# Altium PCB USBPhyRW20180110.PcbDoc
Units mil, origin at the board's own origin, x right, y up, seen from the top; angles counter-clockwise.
Board outline 2170 x 955 mil, 2 copper layers (Top Layer, Bottom Layer); 40 components, 26 nets, 144 pads, 49 vias.
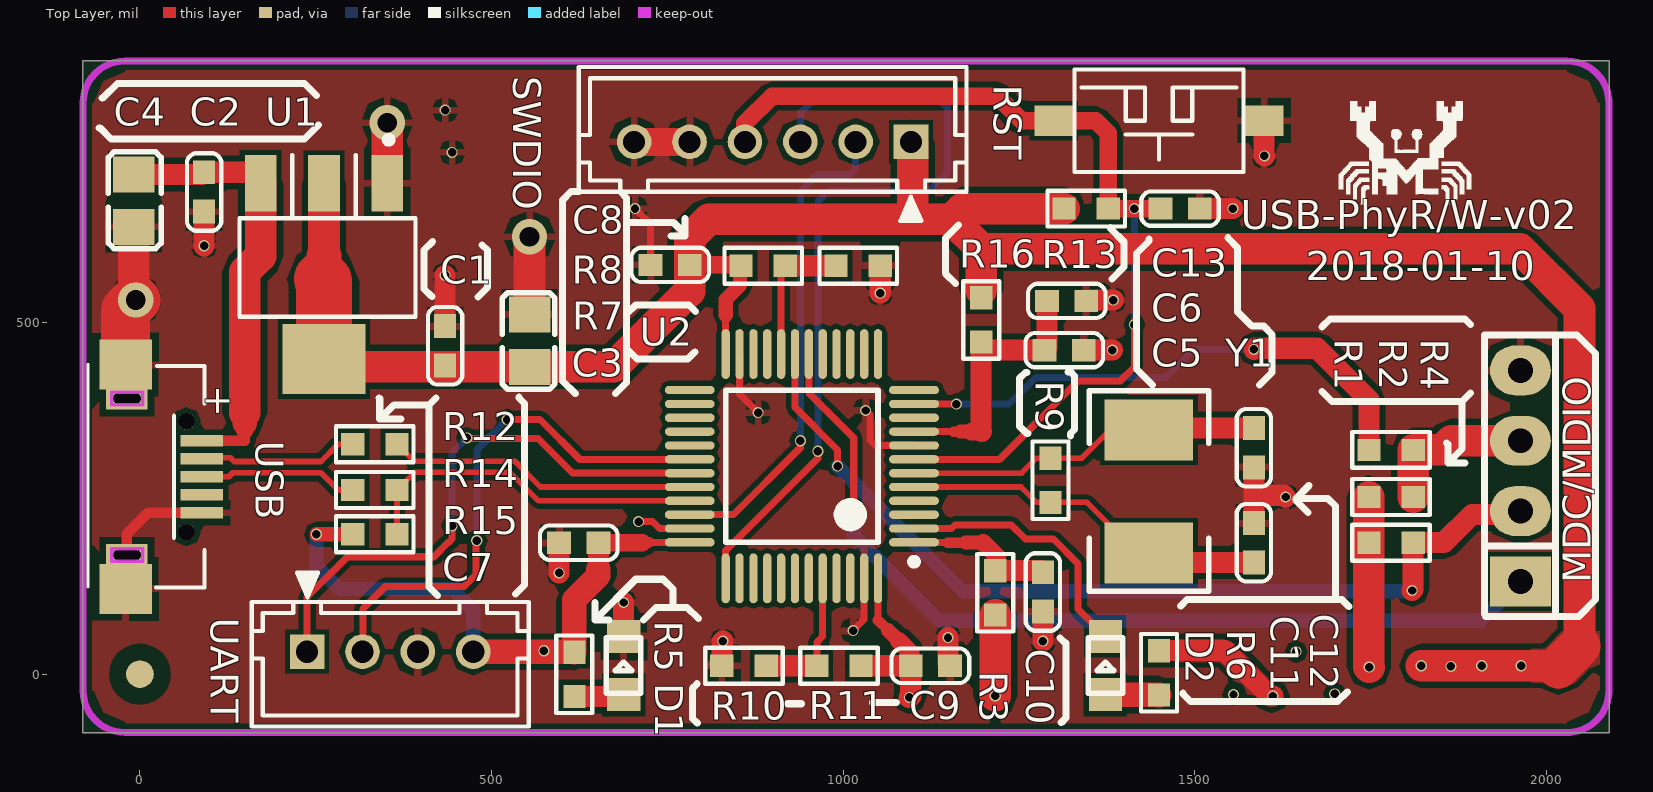
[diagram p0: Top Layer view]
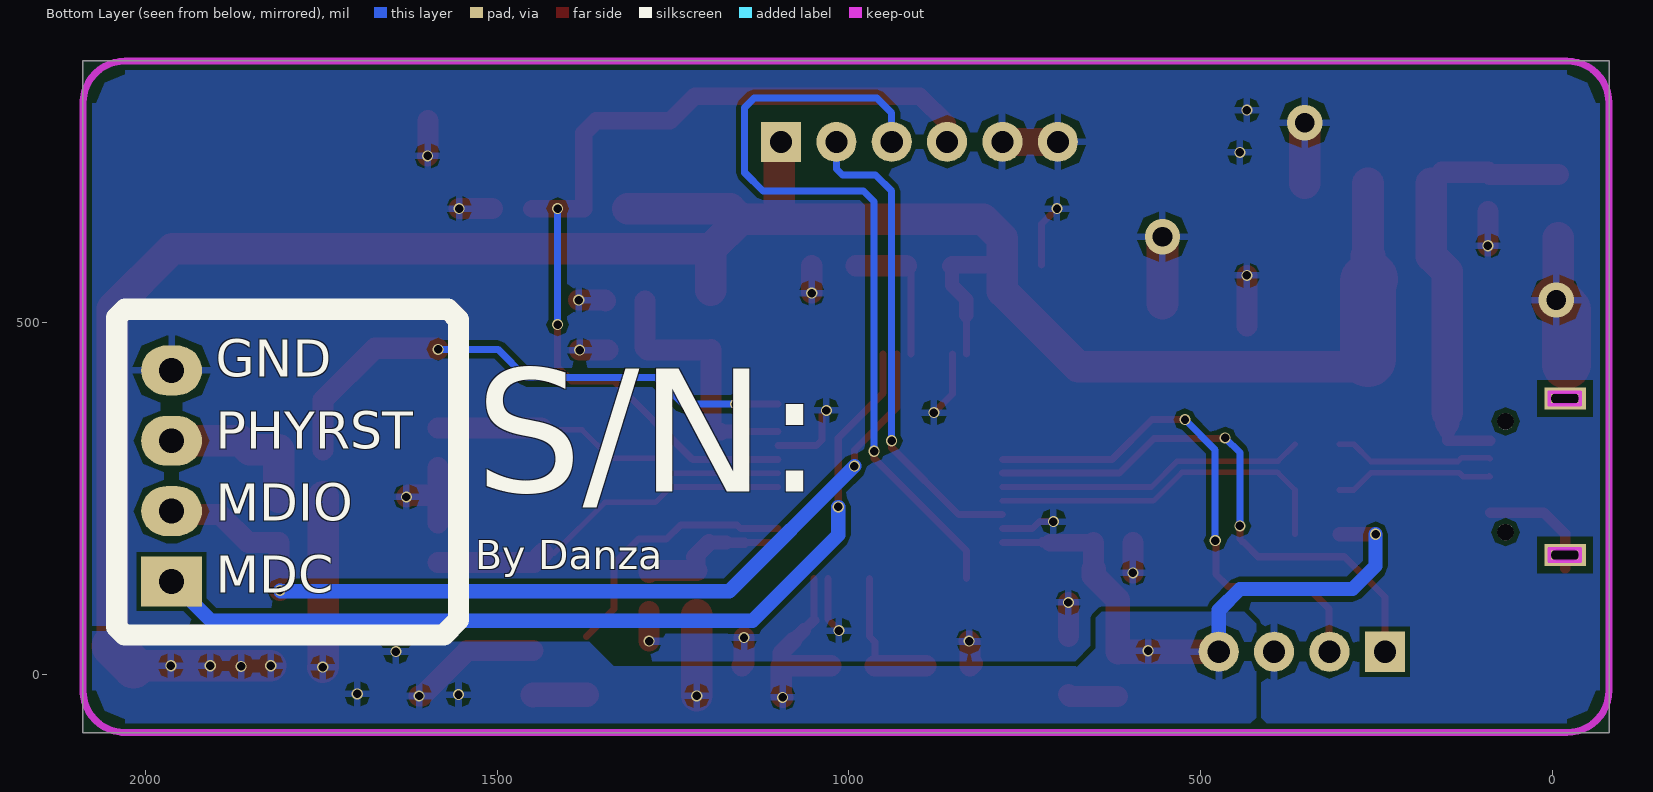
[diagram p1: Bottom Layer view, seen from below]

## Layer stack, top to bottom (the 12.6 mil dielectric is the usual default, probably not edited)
Top Solder: solder mask 0.4, Solder Resist, Dk 3.5
Top Layer: signal copper 1.4
Dielectric 1: dielectric 12.6, FR-4, Dk 4.8
Bottom Layer: signal copper 1.4
Bottom Solder: solder mask 0.4, Solder Resist, Dk 3.5

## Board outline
754,872 2089,872 2089,-63 2089,-73 2089,-83 -81,-83 -81,862 -81,872

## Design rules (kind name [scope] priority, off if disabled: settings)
Clearance [All] p1: gap=7
ComponentClearance [All] p1: gap=3 collisioncheckmode=3 verticalgap=7 showdistances=FALSE
DiffPairsRouting [All] p1: maxlimit=8 minlimit=8 mostfreqgap=8 toplayer_minwidth=8 toplayer_maxwidth=30 toplayer_prefwidth=15 bottomlayer_minwidth=8 bottomlayer_maxwidth=30 bottomlayer_prefwidth=15 maxuncoupledlength=500
PolygonConnect [All] p1: connectstyle=Relief reliefconductorwidth=10 reliefentries=4 polygonreliefangle="90 Angle" airgapwidth=10
RoutingVias [All] p1: holewidth=28 width=50 viastyle="Through Hole" minholewidth=10 minwidth=10 maxholewidth=100 maxwidth=100
SilkToSilkClearance [All] p1 off: silktosilkclearance=10
SolderMaskExpansion [All] p1: expansion=4
Width [All] p1: maxlimit=100 minlimit=8 preferedwidth=10 minimp=50.000000 maximp=50.000000 favimp=50.000000
27 further rules are at their usual default settings.

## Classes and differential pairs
component class CoreBoard: C1 C2 C3 C4 C5 C6 C7 C8 C9 C10 C11 C12 C13 D1 D2 MDC/MDIO/RST#/GND R1 R2 R3 R4 R5 R6 R7 R9 R10 R12 R13 R14 r16 RST SWDIO U1 UART USB Y1
differential pair CLK8M: +OSC_OUT -OSC_IN
differential pair USB_2: +DM_PA11 -DP_PA12
differential pair USB_1: +NetR12_2 -NetR14_2

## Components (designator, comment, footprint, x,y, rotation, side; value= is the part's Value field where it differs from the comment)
C1 "0.1uf" C0603 434,467 r90 top
C2 "0.1uf" C0603 91.24,685.74 r270 top
C3 "10uf" CAP-0805 554,437 r90 top
C4 "10uf" CAP-0805 -8.76,710.74 r270 top
C5 "1uf" C0603 1314.2,460.74 r0 top
C6 "0.1uf" C0603 1317.74,530.74 r0 top
C7 "0.1uf" C0603 624,187 r180 top
C8 "0.1uf" C0603 754,582 r180 top
C9 "0.1uf" C0603 1124,12 r0 top
C10 "0.1uf" C0603 1284,117 r270 top
C11 "20pF" C0603 1584,187 r90 top
C12 "20pF" C0603 1584,322 r90 top
C13 "0.1uf" C0603 1479,662 r180 top
D1 "LED-GREEN" LED-0805 687.74,9.76 r270 top
D2 "LED-GREEN" LED-0805 1372.74,9.76 r270 top
MDC/MDIO "CN_UART" SIP4P-2.54mm 1963,132 r0 top (schematic designator CN3)
R1 "1.5K/NC" R0603 1779,187 r180 top
R2 "50k/NC" R0603 1779,252 r0 top
R3 "0R/NC" R0603 1216.24,115.74 r270 top
R4 "0R" R0603 1779,319 r0 top
R5 "1K" R0603 617.74,-0.24 r270 top
R6 "1K" R0603 1449,2 r270 top
R7 "10K" R0603 1021.24,580.82 r180 top
R8 "10K/NC" R0603 886.24,580.82 r180 top
R9 "1M" R0603 1294.75,275.74 r270 top
R10 "10K" R0603 859,12 r0 top
R11 "10K/NC" R0603 994,12 r0 top
R12 "20R" R0603 334,327 r180 top
R13 "10K" R0603 1345.5,662 r180 top
R14 "20R" R0603 334,262 r180 top
R15 "4K7" R0603 334,199 r0 top
R16 "0R" R0603 1196.24,503.74 r270 top (schematic designator L1)
RST "KEYPAD/NC" SWITCH_T06B 1449,787 r180 top (schematic designator SW1)
SWDIO "DNP/NC" CON_SIP6BOX_2MM 1096.48,758.97 r180 top (schematic designator SWD)
U1 "LM1117-3.3V" SOT-223 269,577 r180 top
U2 "STM32F101C8T6" LQFP48_N 941.24,295.74 r180 top
UART "CN_UART/NC" CON_SIP4BOX_2MM 237.78,30.03 r0 top (schematic designator CN1)
USB "MICROUSB" MICRO-USB 1.24,280.74 r270 top
Y1 "8M" 5032-2P 1434.75,260.74 r270 top
? "Comment" MARK 0,0 r270 top

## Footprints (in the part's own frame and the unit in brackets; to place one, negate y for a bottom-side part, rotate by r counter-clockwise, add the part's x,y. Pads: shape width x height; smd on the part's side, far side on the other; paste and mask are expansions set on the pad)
5032-2P [mm]
  rect 2.2x3.2 smd: 1(-2.2,0) 2(2.25,0)
  silkscreen extent -3.62,-2.16 3.62,2.16
C0603 [mm]
  rect 0.86x0.8 smd: 1(-0.71,0) 2(0.71,0)
  silkscreen extent -1.4,-0.62 1.4,0.62
CAP-0805 [mm]
  rect 1.3x1.5 smd: 1(0,0) 2(1.9,0)
  silkscreen extent -0.82,-0.91 2.68,0.99
CON_SIP4BOX_2MM [mm]
  rect 1.25x1.25 / inner rect 1.25x1.25 / far side rect 1.45x1.45 hole 0.8: 1(0,0.05)
  round 1.25 / inner round 1.25 / far side round 1.45 hole 0.8: 2(2,0.05) 3(4,0.05) 4(6,0.05)
  silkscreen extent -2,-2.65 8,2.91
CON_SIP6BOX_2MM [mm]
  rect 1.25x1.25 / inner rect 1.25x1.25 / far side rect 1.45x1.45 hole 0.8: 1(0,0.05)
  round 1.25 / inner round 1.25 / far side round 1.45 hole 0.8: 2(2,0.05) 3(4,0.05) 4(6,0.05) 5(8,0.05) 6(10,0.05)
  silkscreen extent -2,-2.65 12,2.91
LED-0805 [mm]
  rect 1.2x1.2 smd: 1(-1.116,0.003) 2(0.984,0.003)
  silkscreen extent -1.07,-0.62 0.93,0.63
LQFP48_N [mm]
  oval 1.8x0.3 smd: 1(-4.05,2.75) 2(-4.05,2.25) 3(-4.05,1.75) 4(-4.05,1.25) 5(-4.05,0.75) 6(-4.05,0.25) 7(-4.05,-0.25) 8(-4.05,-0.75) 9(-4.05,-1.25) 10(-4.05,-1.75) 11(-4.05,-2.25) 12(-4.05,-2.75) 25(4.05,-2.75) 26(4.05,-2.25) 27(4.05,-1.75) 28(4.05,-1.25) 29(4.05,-0.75) 30(4.05,-0.25) 31(4.05,0.25) 32(4.05,0.75) 33(4.05,1.25) 34(4.05,1.75) 35(4.05,2.25) 36(4.05,2.75)
  oval 0.3x1.8 smd: 13(-2.75,-4.05) 14(-2.25,-4.05) 15(-1.75,-4.05) 16(-1.25,-4.05) 17(-0.75,-4.05) 18(-0.25,-4.05) 19(0.25,-4.05) 20(0.75,-4.05) 21(1.25,-4.05) 22(1.75,-4.05) 23(2.25,-4.05) 24(2.75,-4.05) 37(2.75,4.05) 38(2.25,4.05) 39(1.75,4.05) 40(1.25,4.05) 41(0.75,4.05) 42(0.25,4.05) 43(-0.25,4.05) 44(-0.75,4.05) 45(-1.25,4.05) 46(-1.75,4.05) 47(-2.25,4.05) 48(-2.75,4.05)
  silkscreen extent -4.18,-2.75 2.75,3.57
MARK [mm]
  round 1 smd paste-1.016 mask+0.5: ""(0,0)
  Top Layer pour cut-out: -1.109,0 -1.072,-0.287 -0.961,-0.555 -0.785,-0.785 -0.555,-0.961 -0.287,-1.072 0,-1.109 0,-1.109 0.287,-1.072 0.555,-0.961 0.785,-0.785 0.961,-0.555 1.072,-0.287 1.109,0 1.109,0 1.072,0.287 0.961,0.555 0.785,0.785 0.555,0.961 0.287,1.072 0,1.109 0,1.109 -0.287,1.072 -0.555,0.961 -0.785,0.785 -0.961,0.555 -1.072,0.287 -1.109,0
MICRO-USB [mm]
  rect 0.4x1.55 smd: 1(-1.3,2.2) 2(-0.65,2.2) 3(0,2.2) 4(0.65,2.2) 5(1.3,2.2)
  rect 1.8x1.9 smd: 6(-4.05,-0.55) 6(4.05,-0.55)
  rect 0.8x1.5 hole 0.4 slot 1 at 90 deg: 6(-2.825,-0.5) 6(2.825,-0.5)
  round 0.6 hole 0.6 unplated: ""(-2,1.65) ""(2,1.65)
  Keep-Out Layer lines w0.127: 3.054,-1.043 3.054,0.075 2.596,0.075 2.596,-1.043 3.054,-1.043 ; -2.596,-1.043 -2.596,0.075 -3.054,0.075 -3.054,-1.043 -2.596,-1.043
  silkscreen extent -4.06,-1.91 4,2.3
R0603 [mm]
  rect 0.84x0.8 smd: 1(-0.8,0) 2(0.8,0)
  silkscreen extent -1.4,-0.65 1.4,0.65
SIP4P-2.54mm [mm]
  rect 2.2x1.8 hole 0.9: 1(0,0)
  oval 2.2x1.8 hole 0.9: 2(0,2.54) 3(0,5.08) 4(0,7.62)
  silkscreen extent -1.29,-1.27 1.27,8.9
SOT-223 [mil]
  rect 45x80 smd: 1(-82.76,-121.26) 2(7.24,-121.26) 3(97.24,-121.26)
  rect 118x100 smd: 4(7.24,128.74)
  silkscreen extent -123,-188 127,69
SWITCH_T06B [mm]
  rect 1.4x1.1 smd: 1(-3.8,0) 2(3.8,0)
  silkscreen extent -3.05,-1.85 3.05,1.85

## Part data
C1 C2 C5 C6 C7 C8 C9 C10 C13: library part CAP_1, "Capacitor"
C3 C4: library part CAPACITOR, "Capacitor"
C11 C12: library part CAP, "Capacitor"
D1 D2: library part LED
MDC/MDIO UART: library part CON4
R1 R2 R3 R4 R5 R6 R7 R8 R9 R10 R11 R12 R13 R14: library part RES1
R16: library part INDUCTOR1
RST: library part PUSHBUTTON_TSKB-2L_0
SWDIO: library part CON6
U1: library part LM1117
U2: "STM32 ARM-based 32-bit MCU with 64 Kbytes Flash, 48-pin LQFP, Industrial Temperature"
Y1: library part CRYSTAL, "Crystal"

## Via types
v1: diameter 15.75, hole 12, Top Layer to Bottom Layer, 46 vias
v2: diameter 50, hole 28, Top Layer to Bottom Layer, 3 vias

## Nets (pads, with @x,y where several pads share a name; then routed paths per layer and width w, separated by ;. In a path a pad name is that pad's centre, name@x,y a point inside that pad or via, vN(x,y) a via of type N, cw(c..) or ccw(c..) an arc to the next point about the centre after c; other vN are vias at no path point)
BOOT0: R10.2 R11.1 U2.44 | length 199.7
  Top Layer w10: R11.1 962.5,45.5 970.77,53.77 U2.44
  Top Layer w30: R10.2 R11.1
BOOT1: R7.2 R8.1 U2.20 | length 200.1
  Top Layer w10: U2.20 911.72,574.8 R8.1
  Top Layer w30: R8.1 R7.2
DM_PA11: R12.1 U2.32 | length 441.5
  Top Layer w8: R12.1 389.5,303 533,303 569.79,266.21 U2.32
DP_PA12: R14.1 R15.2 U2.33 | length 506.4
  Top Layer w8: R15.2 R14.1 390.5,287 526.37,287 566.84,246.53 U2.33
GND: C1.2 C2.2 C3.2 C4.2 C5.2 C6.2 C7.2 C8.2 C9.2 C10.2 C11.2 C12.1 C13.1 D1.1 MDC/MDIO.4 R7.1 R10.1 RST.1 SWDIO.5 SWDIO.6 U1.1 U2.8 U2.23 U2.35 U2.47 UART.3 USB.5 USB.6 | length 1742.8
  Top Layer w10: v1(704,662) 726.05,639.95 C8.2 ; v1(709,217) 729,217 738.84,207.16 U2.35 ; U2.23 852.66,398.34 v1(879,372) ; v1(1014,62) 1029.83,77.83 U2.47 ; v1(1032,375) 1038,369 1038,333 1045.73,325.27 U2.8
  Top Layer w15: USB.6@-18.44,150.52 -18.44,169.52 -18.44,199.56 11.56,229.56 USB.5
  Top Layer w30: v1(91.24,609.24) C2.2 ; C1.2 v1(434,567) ; v1(596.05,144.05) C7.2 ; D1.1 v1(687.86,102) ; R10.1@824,15.5 R10.1 827.5,45.5 v1(829,47) ; v1(1052.74,542) R7.1 ; v1(1149,52) 1149,14.95 C9.2 ; v1(1284,47) C10.2 ; C5.2 v1(1382.74,460.74) ; C6.2 1346.95,532 v1(1384,532) ; C13.1 v1(1554,662) ; C11.2 1584,254.5 ; C12.1 1584,254.5 ; RST.1 1598.61,737.39 v1(1599,737) ; v1(1629,252) 1626.5,254.5 1584,254.5
  Top Layer w40: SWDIO.6 SWDIO.5
  Top Layer w45: C4.2@-8.76,620.74 -8.76,534.76 v2(-6,532) ; U1.1 v2(351.76,784.24) ; C3.2@554,527 v2(554,622)
  Top Layer w70: USB.6@-20.41,440.19 -20.41,517.59 v2(-6,532)
  other v1: 444,742 434,802
NetD1_2: D1.2 R5.2 | length 71.3
  Top Layer w30: R5.2 685.1,-31.74 D1.2
NetD2_2: D2.2 R6.2 | length 76.4
  Top Layer w35: D2.2 1448.49,-28.98 R6.2
NetQ1_1: 
NetR12_2: R12.2 USB.2 | length 227.8
  Top Layer w8: USB.2 89.53,308 128.5,308 134,302.5 257.47,302.5 281.97,327 R12.2
NetR14_2: R14.2 USB.3 | length 229
  Top Layer w8: USB.3@89.12,282 USB.3 126.24,280.74 132,286.5 257.47,286.5 281.97,262 R14.2
NRST: C13.2 R13.1 RST.2 SWDIO.4 U2.7 | length 1359.8
  Top Layer w10: U2.7 1222.58,305.58 1334,417 1394,417 1414,437 v1(1414,497) v1@1414,502
  Top Layer w25: SWDIO.4 860.26,783.26 899,822 1219,822 1254,787 RST.2 1359,787 1376.99,769.01 R13.1 v1(1414.02,662) C13.2
  Bottom Layer w10: v1(1414,497) v1(1414.02,662)
OSC_IN: C11.1 R9.2 U2.5 Y1.2 | length 527.7
  Top Layer w8: U2.5 1253.03,266.21 1275,244.24 R9.2 1346.76,244.24 1418.84,172.16 Y1.2
  Top Layer w30: Y1.2 1447.86,159.05 C11.1
OSC_OUT: C12.2 R9.1 U2.6 Y1.1 | length 509.8
  Top Layer w8: U2.6 1253.66,285.9 1275,307.24 R9.1 1339.24,307.24 1379.35,347.35 Y1.1
  Top Layer w30: Y1.1 1437.35,349.95 C12.2
PC13: D2.1 U2.2 | length 377.5
  Top Layer w10: U2.2 1154.16,207.16 1159,212 1239,212 1259,192 1299,192 1334,157 1334,92.55 D2.1
PHYRST: R4.1 U2.11 | length 781.5
  Top Layer w10: U2.11 v1@1161.32,384.32
  Top Layer w30: v1(1584,462) 1585.5,463.5 1674,463.5 1747.5,389.99 R4.1
  Bottom Layer w10: v1(1161,384) 1236,384 1274,422 1459,422 1499,462 v1(1584,462)
PHYRST#: MDC/MDIO.3 R2.2 R4.2 | length 229.5
  Top Layer w45: R2.2 R4.2 ; R4.2@1813.76,315.74 R4.2 ; MDC/MDIO.3 1865,332 1852,319 R4.2
RX1: U2.31 UART.1 | length 808.3
  Top Layer w10: UART.1 237.78,109.78 295,167 418,167 439,188 440,188 444,192 v1(444,211) ; v1(465,336) 466,335 566,335 615.1,285.9 U2.31
  Bottom Layer w10: v1(444,211) 444,315 v1(465,336)
SMIMDC: MDC/MDIO.1 U2.18 | length 1305.4
  Top Layer w10: U2.18 951.09,399.91 1015,336 v1(1015,238)
  Bottom Layer w20: v1(1015,238) 1015,198 1137,76 1907,76 MDC/MDIO.1
SMIMDIO: MDC/MDIO.2 R1.1 U2.19 | length 1315.2
  Top Layer w10: U2.19 931.4,379.6 992,319 v1(992,296)
  Top Layer w30: v1(1809,119) 1810.5,120.5 R1.1 1854,187 1894,227 1958,227 MDC/MDIO.2
  Bottom Layer w20: v1(992,296) 1170,118 1808,118 v1(1809,119)
SWCLK: SWDIO.3 U2.37 | length 1148
  Top Layer w10: U2.37 832.98,175.98 964,307 v1(964,317)
  Bottom Layer w10: SWDIO.3 939,798 960,819 1135,819 1148,806 1148,713 1122,687 979.1,687 964,671.9 v1(964,317)
SWDIO: SWDIO.2 U2.34 | length 691.9
  Top Layer w10: U2.34 843.84,226.84 939,322 v1(939,332)
  Bottom Layer w10: v1(939,332) 939,687 962,710 1009.21,710 1017.74,718.53 SWDIO.2
TX1: U2.30 UART.2 | length 763.9
  Top Layer w10: UART.2 317,32.48 317,93 349,125 461,125 478,142 478,189 v1(479,190) ; v1(522,362) 569,362 625.42,305.58 U2.30
  Bottom Layer w10: v1(479,190) 479,319 v1(522,362)
USB_5V: C2.1 C4.1 U1.3 USB.1 | length 625
  Top Layer w15: USB.1 148.92,331.92 148.92,346.92
  Top Layer w25: 148.92,346.92 148.92,356.92
  Top Layer w30: C4.1 88.29,710.74 C2.1 156.32,713.69 U1.3
  Top Layer w35: 148.92,356.92 148.92,371.92
  Top Layer w45: 148.92,371.92 148.92,426.92 149,427 149,572 171.76,594.76 U1.3
VBAT: C10.1 R3.1 U2.1 | length 216.4
  Top Layer w10: U2.1 1101.17,187 1149,187
  Top Layer w15: 1149,187 1174,187
  Top Layer w20: 1174,187 1199,187
  Top Layer w25: 1199,187 1219,167 1216.24,164.24 R3.1
  Top Layer w30: R3.1 1281.72,147.24 C10.1
VCC_3V3: C1.1 C3.1 C7.1 C8.1 C9.1 R1.2 R2.1 R3.2 R5.1 R6.1 R8.2 R11.2 R13.2 R15.1 R16.1 SWDIO.1 U1.2 U1.4 U2.24 U2.36 U2.48 UART.4 | length 5143.4
  Top Layer w10: 724.47,187.47 U2.36 ; U2.24 832.98,505.98 ; 1049.51,77 U2.48
  Top Layer w15: 714.47,187.47 724.47,187.47 ; 832.98,505.98 832.98,510.98 ; 1049.51,77 1064,62.51
  Top Layer w20: v1(251,199) R15.1 ; 714,187 714.47,187.47 ; 832.98,510.98 832.98,532.98 853.57,553.57 R8.2@853.57,582 ; 1064,62.51 1079,47.51
  Top Layer w25: C7.1 714,187 ; C8.1 853.57,582 R8.2 ; 1079,47.51 1096.05,30.46 C9.1
  Top Layer w30: 651.95,149.05 C7.1 ; R11.2 C9.1 1096.05,-30.95 v1(1094,-33) ; R6.1 1542.5,33.5 1607,-31 v1(1611,-31)
  Top Layer w35: UART.4 616.99,32 R5.1 617.74,105.74 651.95,139.95 651.95,149.05
  Top Layer w45: U1.4 273.02,437 C3.1 674,437 781.95,544.95 C8.1 781.95,619.95 809,647 1099,647 ; 261.76,594.76 U1.2 ; SWDIO.1 1099,754.48 1099,647 ; R16.1@1196.24,545.74 1196.24,604.76 ; v1(1216.24,-30.76) R3.2 ; R13.2 1169,662 1154,647 ; R2.1 R1.2 1747.5,10.5 v1(1748,10) ; v1(1822,12) v1(1908,12) v1(1964,12) 2015,12 2017,10 ; 2047,40 2047,520 1962.24,604.76 1196.24,604.76 ; 1099,647 1154,647 ; 1154,647 1196.24,604.76
  Top Layer w50: 261.76,564.24 261.76,594.76
  Top Layer w55: 259,561.49 261.76,564.24
  Top Layer w60: 2017,10 2047,40
  Top Layer w80: 259,561.49 261.76,558.73 U1.4
  Bottom Layer w20: v1(251,199) 251,154 284,121 444,121 474,91 UART.4
  other v1: 1555,-29 1699,-28 1864,11 1644,32 574.4,33.32
VDDA: C5.1 C6.1 R16.2 U2.9 | length 375.2
  Top Layer w10: U2.9 1156.95,344.95
  Top Layer w15: 1156.95,344.95 1166.95,344.95
  Top Layer w20: 1166.95,344.95 1181.95,344.95
  Top Layer w25: 1181.95,344.95 1196.95,344.95
  Top Layer w30: 1196.95,344.95 1196.24,345.66 1196.24,461.74 1197.24,460.74 C5.1 1289.79,464.28 C6.1
pads on no net: ?. U2.3 U2.4 U2.10 U2.12 U2.13 U2.14 U2.15 U2.16 U2.17 U2.21 U2.22 U2.25 U2.26 U2.27 U2.28 U2.29 U2.38 U2.39 U2.40 U2.41 U2.42 U2.43 U2.45 U2.46 USB. USB.4

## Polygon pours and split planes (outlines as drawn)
GND on Top Layer "GND_L01_P010" (solid, remove dead copper, pour order 10): -81,872 -81,-83 2089,-83 2089,-77 2089,872 1933,872 -81,872
VCC_3V3 on Top Layer "VCC_3V3_L01_P016" (solid, remove dead copper, pour order 16): 1610,56 1613,59 2030,59 2068,59 2076,51 2077,50 2077,-35 2075,-35 2040,-70 2036,-74 1848,-74 1612,-74 1610,-72
VCC_3V3 on Top Layer "VCC_3V3_L01_P018" (solid, remove dead copper, pour order 18): 1448.33,57.03 1448,56.7 1448,-70 2042,-70 2077,-35 2077,61 1452.69,61 1449,57.31
VCC_3V3 on Bottom Layer "VCC_3V3_L02_P012" (solid, remove dead copper, pour order 12): 2084,61 1912,61 1897,46 1671,46 1369,46 1337,14 1334,11 1227,11 677,11 676,10 649,37 649,49 649,80 648,81 640,89 489,89 438,89 427,78 421,72 421,-15 421,-62 439,-80 440,-81 1325,-81 2083,-81
GND on Bottom Layer "GND_L02_P014" (solid, remove dead copper, pour order 14): 2090,-83 2090,871 2089,872 -81,872 -81,-83 2090,-83

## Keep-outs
Keep-Out Layer:
  lines w10: 2029,-83 ccw(c2029,-23) 2089,-23 ; 2034,-83 -6,-83 -21,-83 cw(c-21,-23) -81,-23 -81,-8 -81,812 cw(c-21,812) -21,872 2029,872 cw(c2029,812) 2089,812 ; 2089,-28 2089,817

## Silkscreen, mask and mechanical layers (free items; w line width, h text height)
Top Overlay:
  drawing of 797 lines, arcs and shapes, not listed
  text "USB-PhyR/W-v02" at 1565,619 h70
  text "2018-01-10" at 1658,547 h70
Bottom Overlay:
  lines w30: 1993,519 2029,519 2041,507 2041,67 2030,56 1576,56 1555,77 1555,504 1570,519 2011,519
  text "GND" at 1900.2,405 h90
  text "PHYRST" at 1900.2,302.7 h90
  text "S/N:" at 1531,202 h300
  text "MDIO" at 1900.2,200.39 h90
  text "By Danza" at 1531,136 h70
  text "MDC" at 1900.2,98 h90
